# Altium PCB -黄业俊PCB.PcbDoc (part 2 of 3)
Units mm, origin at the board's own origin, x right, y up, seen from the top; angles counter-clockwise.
Board outline 130 x 100.6 mm, 2 copper layers (Top Layer, Bottom Layer); 47 components, 24 nets, 117 pads, 0 vias.
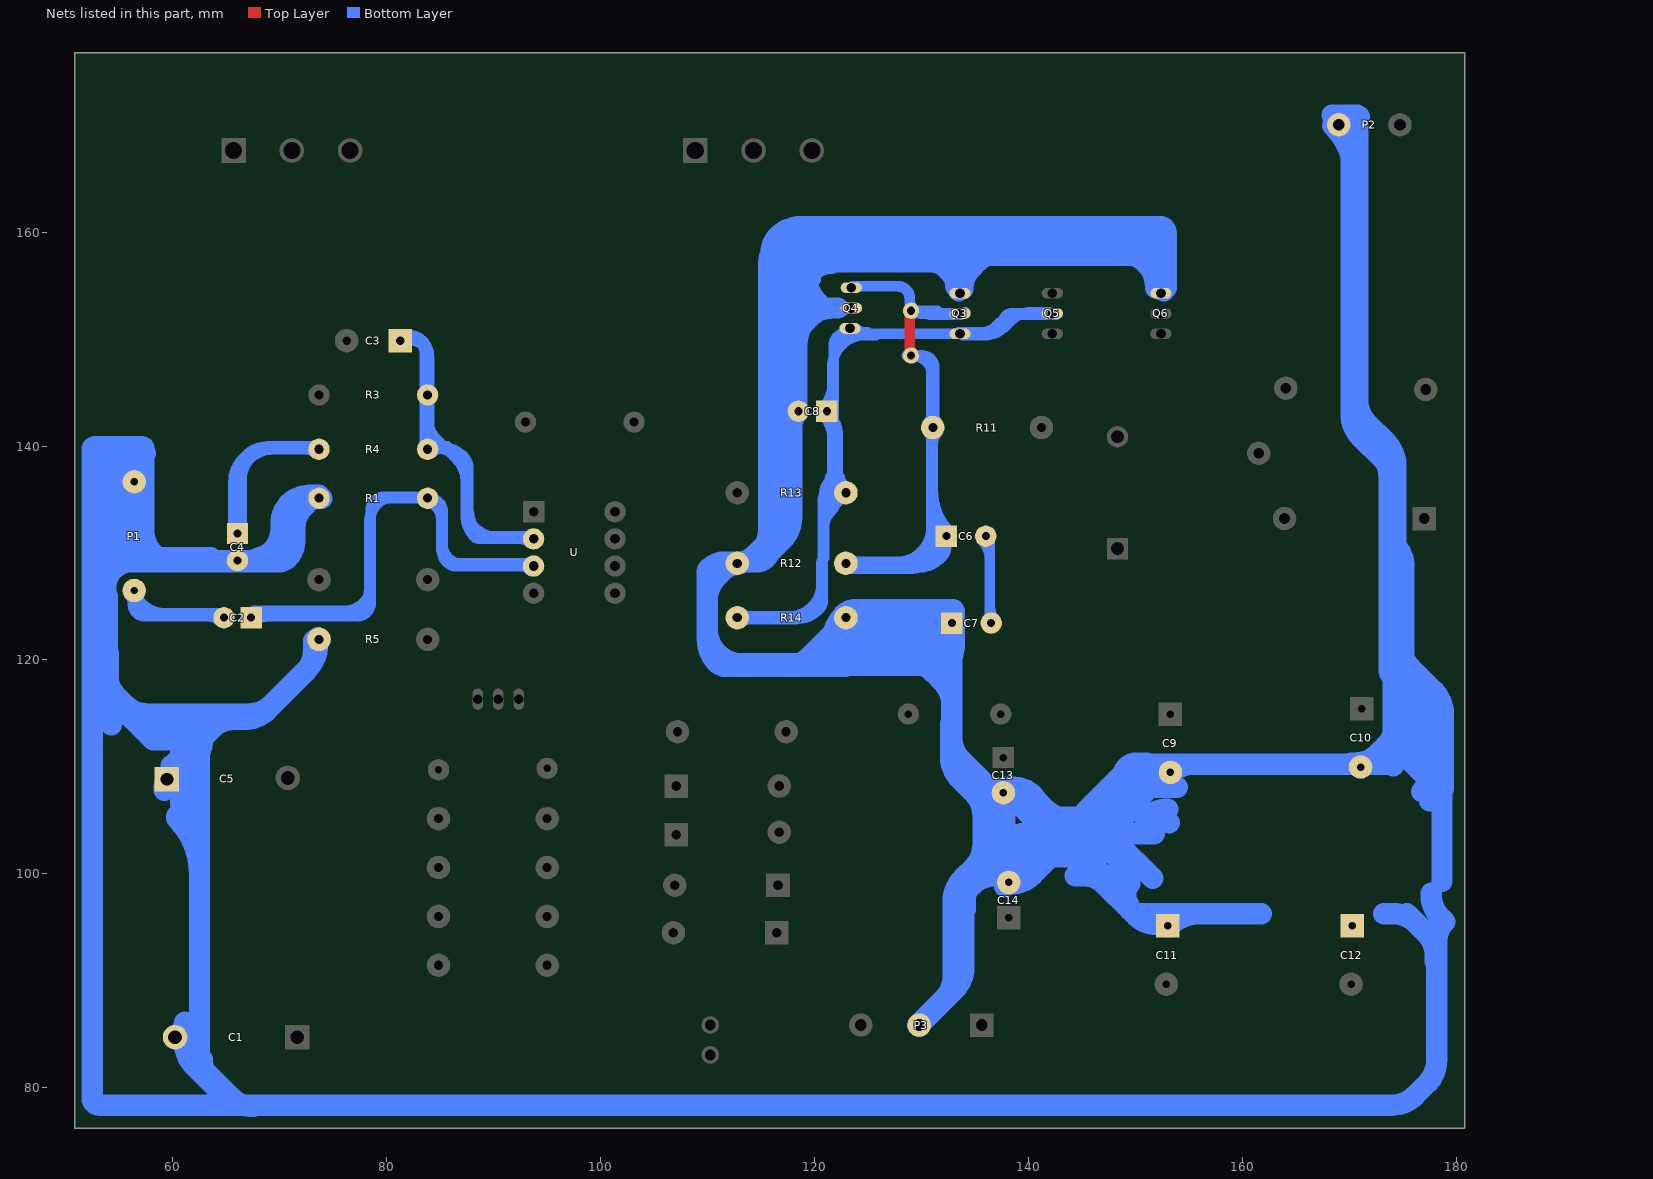
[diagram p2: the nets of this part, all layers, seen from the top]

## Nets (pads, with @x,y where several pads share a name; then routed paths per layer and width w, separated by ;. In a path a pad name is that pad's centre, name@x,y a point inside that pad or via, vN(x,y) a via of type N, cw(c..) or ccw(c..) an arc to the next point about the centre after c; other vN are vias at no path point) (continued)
GND: C1.2 C4.2 C5.1 C7.1 C8.2 C9.2 C10.2 C11.1 C12.1 C13.2 C14.2 P1.1 P2.2 P3.2 Q3.1 Q4.2 Q6.1 R1.2 R5.1 R12.2 R14.2 | length 2136.7
  Bottom Layer w1: 116.713,152.654 Q4.2@122.704,152.654 ; 117.512,147.992 ccw(c117.295,148.209) 117.602,148.209 cw(c120.668,148.209) 118.5,150.377 120.65,152.527 ; 120.105,155.538 cw(c119.888,155.755) 119.888,155.448 ccw(c122.034,155.448) 120.517,153.93 121.232,153.215 ccw(c121.666,153.648) 121.666,153.035 ; 122.331,152.654 ccw(c122.331,153.521) Q4.2@122.944,152.908 ; 122.331,152.654 ccw(c122.331,153.521) Q4.2@122.944,152.908 ; 122.331,152.654 ccw(c122.331,153.521) Q4.2@122.944,152.908 ; 122.331,152.654 ccw(c122.331,153.521) Q4.2@122.944,152.908
  Bottom Layer w2: 52.451,133.604 52.451,139.802 ccw(c52.448,139.802) 52.45,139.804 cw(c52.812,139.443) 52.812,139.954 55.775,139.954 cw(c55.775,139.087) 56.388,139.7 cw(c56.081,139.393) 56.515,139.393 56.515,138.049 ccw(c57.128,137.436) 56.261,137.436 56.261,131.445 ; 52.832,139.446 57.097,139.446 cw(c57.097,139.012) 57.404,139.319 ccw(c57.711,139.012) 57.277,139.012 57.277,132.08 ccw(c60.343,132.08) 58.175,129.912 ccw(c59.073,130.81) 59.073,129.54 63.54,129.54 ; 53.34,129.023 cw(c53.848,128.143) 53.389,129.049 cw(c53.848,128.143) 53.848,129.159 70.104,129.159 ; 53.594,126.55 ccw(c54.461,126.55) 53.848,125.937 53.848,118.745 ccw(c56.914,118.745) 54.746,116.577 55.49,115.833 ccw(c57.658,118.001) 57.658,114.935 67.564,114.935 ; 53.721,121.539 53.721,126.877 cw(c55.858,126.877) 54.347,128.388 cw(c56.515,126.22) 56.515,129.286 ; 53.721,139.954 56.97,139.954 cw(c56.97,139.52) 57.277,139.827 57.277,136.735 cw(c55.543,136.735) 56.769,135.509 56.509,135.249 ccw(c58.026,133.731) 55.88,133.731 ; 53.975,120.65 53.975,117.983 ccw(c57.041,117.983) 54.873,115.815 58.166,112.522 59.182,112.522 ccw(c59.182,115.588) 61.35,113.42 ; 53.975,135.001 53.975,132.842 ccw(c57.041,132.842) 54.873,130.674 55.88,129.667 ; 54.012,136.562 cw(c55.174,135.4) P1.1@56.318,136.58 ; 54.229,130.175 54.229,133.604 cw(c57.295,133.604) 55.127,135.772 P1.1@56.134,136.779 ; 54.238,113.91 cw(c56.406,116.078) 53.34,116.078 53.34,134.063 cw(c55.911,134.063) 54.093,135.881 cw(c56.261,133.713) 56.261,136.779 P1.1@56.388,136.779 ; 54.356,134.112 cw(c55.582,135.338) 53.848,135.338 53.848,135.763 cw(c55.381,135.763) 54.297,136.847 55.155,137.705 cw(c55.372,137.488) 55.372,137.795 ; 54.564,128.605 cw(c56.515,126.654) 56.515,129.413 ; 55.753,114.808 64.135,114.808 ; 55.753,132.969 ccw(c58.819,132.969) 56.651,130.801 57.395,130.057 ccw(c59.563,132.225) 59.563,129.159 61.722,129.159 ; 56.261,114.427 66.675,114.427 ccw(c66.675,117.493) 68.843,115.325 72.254,118.736 ccw(c70.086,120.904) 73.152,120.904 R5.1@73.152,121.793 ; P1.1@56.317,136.581 cw(c54,134.264) 57.277,134.264 ; P1.1@56.317,136.723 ccw(c54,139.04) 57.277,139.04 ; P1.1@56.318,136.723 ccw(c54.066,139.012) 57.277,139.012 ; 56.642,139.954 56.642,132.207 ccw(c59.708,132.207) 57.54,130.039 58.293,129.286 ; 56.896,129.794 ccw(c58.122,131.02) 58.122,129.286 67.183,129.286 ccw(c67.183,132.352) 69.351,130.184 69.587,130.42 ccw(c67.419,132.588) 70.485,132.588 70.485,132.969 ; 56.905,129.912 cw(c59.073,132.08) 56.007,132.08 56.007,133.604 cw(c59.073,133.604) 56.905,135.772 57.023,135.89 57.023,137.331 ccw(c55.289,137.331) 56.515,138.557 ccw(c56.208,138.25) 56.208,138.684 54.737,138.684 ccw(c54.737,135.618) 52.569,137.786 52.451,137.668 52.451,78.92 ccw(c52.885,78.92) 52.578,78.613 ccw(c53.191,79.226) 53.191,78.359 61.341,78.359 ; C5.1@59.182,107.823 cw(c62.248,107.823) 60.08,109.991 63.999,113.91 cw(c66.167,111.742) 66.167,114.808 ; 59.817,110.109 ccw(c59.817,110.416) 60.034,110.199 62.221,112.386 ; 60.071,114.935 67.056,114.935 ccw(c67.056,118.001) 69.224,115.833 72.635,119.244 ccw(c70.467,121.412) 73.533,121.412 R5.1@73.533,122.079 ; C1.2@60.155,84.853 ccw(c59.778,86.106) 61.087,86.106 61.087,84.201 ccw(c64.153,84.201) 61.985,82.033 64.761,79.257 ccw(c66.929,81.425) 66.929,78.359 ; 60.346,105.177 cw(c55.184,100.015) 62.484,100.015 ; 60.346,105.389 ccw(c55.184,110.551) 62.484,110.551 ; 60.706,106.553 60.706,111.655 cw(c61.573,111.655) 60.96,112.268 ; 61.341,107.823 61.341,109.347 cw(c64.407,109.347) 62.239,111.515 ; 61.595,78.359 173.99,78.359 ccw(c173.99,81.425) 176.158,79.257 177.283,80.382 ccw(c175.115,82.55) 178.181,82.55 178.181,93.664 cw(c180.783,93.664) 178.943,95.504 178.571,95.876 cw(c180.739,98.044) 177.673,98.044 177.673,98.171 ; 61.84,110.354 ccw(c59.672,112.522) 62.738,112.522 ; 62.23,111.023 cw(c64.928,111.023) 63.02,112.931 63.726,113.637 cw(c65.634,111.729) 65.634,114.427 66.802,114.427 ; 62.357,86.233 62.357,83.439 ccw(c65.423,83.439) 63.255,81.271 65.396,79.13 ccw(c67.564,81.298) 67.564,78.232 ; 62.484,82.931 62.484,111.252 cw(c65.55,111.252) 63.382,113.42 63.618,113.656 cw(c65.786,111.488) 65.786,114.554 67.183,114.554 ; 62.738,82.652 ccw(c65.436,82.652) 63.528,80.744 65.123,79.149 ccw(c67.031,81.057) 67.031,78.359 67.818,78.359 ; C4.2@66.167,129.286 69.469,129.286 ccw(c69.469,130.556) 70.739,130.556 70.739,133.858 cw(c72.009,133.858) 72.009,135.128 R1.2@73.914,135.128 ; C4.2@66.294,129.159 69.819,129.159 ccw(c69.819,130.46) 70.739,129.54 ccw(c69.206,131.073) 71.374,131.073 71.374,132.207 cw(c74.44,132.207) 72.272,134.375 72.756,134.859 cw(c73.406,134.208) R1.2@73.406,135.128 ; 67.691,129.413 ccw(c67.691,132.479) 69.859,130.311 ; 68.04,129.54 ccw(c68.04,130.248) 68.54,129.747 ccw(c68.54,130.344) 68.962,129.922 69.314,130.274 ccw(c67.406,132.182) 70.104,132.182 70.104,132.82 cw(c72.609,132.82) 70.838,134.592 cw(c72.746,132.684) 72.746,135.382 R1.2@73.66,135.382 ; 72.576,134.679 cw(c73.66,133.595) R1.2@73.66,135.128 ; 73.152,120.784 cw(c74.417,120.784) R5.1@73.715,121.837 ; 111.633,129.032 112.395,129.032 ccw(c112.395,132.098) 114.563,129.93 116.196,131.563 ccw(c114.028,133.731) 117.094,133.731 117.094,153.289 ; R12.2@111.887,129.159 111.642,129.159 ccw(c111.642,126.991) 110.816,128.995 ccw(c111.642,126.991) 110.294,128.689 ccw(c111.642,126.991) 110.109,128.524 ccw(c110.416,128.217) 109.982,128.217 109.982,121.907 ccw(c113.017,121.907) 110.871,119.761 ccw(c111.791,120.681) 111.791,119.38 122.936,119.38 ; 112.141,119.38 117.348,119.38 ccw(c117.348,122.446) 119.516,120.278 121.651,122.413 ccw(c121,123.063) 121.92,123.063 ; R12.2@112.268,129.159 114.554,129.159 ccw(c114.554,130.429) 115.824,130.429 115.824,135.89 cw(c115.951,135.89) 115.951,136.017 115.951,141.224 ccw(c115.951,141.478) 116.205,141.478 ; R12.2@112.522,129.159 113.665,129.159 ccw(c113.665,132.225) 115.833,130.057 116.958,131.182 ccw(c114.79,133.35) 117.856,133.35 117.856,149.956 ccw(c116.555,149.956) 117.475,150.876 117.475,151.13 ; R12.2@112.649,129.032 ccw(c112.649,132.098) 114.817,129.93 ccw(c112.693,132.054) 115.697,132.054 115.697,156.845 cw(c118.763,156.845) 116.595,159.013 116.704,159.122 cw(c118.872,156.954) 118.872,160.02 122.047,160.02 ; R12.2@112.903,129.032 ccw(c112.903,127.192) 111.602,128.493 110.88,127.771 ccw(c113.048,125.603) 109.982,125.603 109.982,123.698 109.982,122.809 ccw(c113.048,122.809) 110.88,120.641 110.989,120.532 ccw(c113.157,122.7) 113.157,119.634 119.454,119.634 ccw(c119.454,120.068) 119.761,119.761 cw(c120.374,119.148) 120.374,120.015 122.958,120.015 ccw(c122.958,120.882) 123.571,120.269 ; 114.173,119.507 131.826,119.507 ; 115.951,139.065 115.951,157.992 cw(c118.088,157.992) 116.577,159.503 cw(c118.745,157.335) 118.745,160.401 136.017,160.401 ; 115.951,155.829 115.951,158.119 cw(c118.088,158.119) 116.577,159.63 cw(c118.745,157.462) 118.745,160.528 136.906,160.528 ; 116.168,156.681 118.101,158.614 cw(c120.269,156.446) 120.269,159.512 121.793,159.512 ; 117.094,139.883 cw(c121.864,139.883) C8.2@118.491,143.256 ; 117.094,146.629 ccw(c121.864,146.629) C8.2@118.491,143.256 ; 117.094,151.511 118.042,152.459 cw(c119.126,151.375) 119.126,152.908 ; 117.744,156.987 118.482,157.725 cw(c120.65,155.557) 120.65,158.623 ; 117.856,141.723 cw(c120.024,141.723) C8.2@118.491,143.256 ; 117.856,144.789 ccw(c120.024,144.789) C8.2@118.491,143.256 ; 117.856,153.416 117.856,154.2 ccw(c116.989,154.2) 117.602,154.813 117.602,155.956 ccw(c117.909,155.956) 117.692,155.739 120.396,153.035 ccw(c120.089,152.728) 120.089,153.162 120.015,153.162 ccw(c118.789,153.162) 119.656,154.029 119.38,154.305 cw(c119.687,154.612) 119.253,154.612 119.253,155.448 cw(c120.479,155.448) 119.612,156.315 120.006,156.709 cw(c122.174,154.541) 122.174,157.607 124.841,157.607 ; 117.983,150.876 119.38,152.273 ; C8.2@118.364,143.637 118.364,149.606 cw(c121.43,149.606) 119.262,151.774 119.498,152.01 cw(c121.666,149.842) 121.666,152.908 122.174,152.908 119.634,152.908 ; 118.999,157.861 131.944,157.861 cw(c131.944,155.693) 133.477,157.226 cw(c133.17,156.919) 133.604,156.919 133.678,156.919 ccw(c133.678,159.985) 135.846,157.817 ; 119.244,156.328 cw(c121.412,154.16) 121.412,157.226 128.007,157.226 ccw(c128.007,159.394) 129.54,157.861 ; 119.244,156.709 cw(c121.412,154.541) 121.412,157.607 123.317,157.607 ; 119.371,156.582 cw(c121.539,154.414) 121.539,157.48 127,157.48 ; 119.56,156.644 120.65,157.734 ccw(c121.876,158.96) 121.876,157.226 132.842,157.226 ; 119.77,156.346 cw(c121.588,154.528) 121.588,157.099 ; 119.888,160.528 152.01,160.528 ; 122.047,121.564 cw(c125.324,121.564) 123.007,123.881 cw(c125.017,121.871) 125.017,124.714 ; 122.047,122.602 cw(c123.363,122.602) R14.2@122.966,123.857 ; R14.2@122.682,124.206 cw(c123.908,122.98) 123.908,124.714 130.801,124.714 cw(c130.801,122.546) 132.334,124.079 cw(c131.108,122.853) 132.842,122.853 cw(c130.897,122.853) 132.272,121.477 ccw(c131.51,120.715) 131.51,121.793 ; R14.2@122.809,124.079 131.699,124.079 ; R14.2@123.317,123.19 129.667,123.19 cw(c129.667,122.555) 130.302,122.555 130.302,122.047 cw(c129.032,122.047) 129.032,120.777 123.952,120.777 cw(c123.952,121.285) 123.444,121.285 ; 124.46,119.761 128.905,119.761 cw(c128.905,116.695) 131.073,118.863 131.944,117.992 cw(c129.776,115.824) 132.842,115.824 132.842,112.776 ; 125.017,123.19 cw(c125.017,126.033) 123.007,124.023 ccw(c127.776,128.792) 127.776,122.047 ; 125.984,158.623 130.429,158.623 cw(c130.429,155.557) 132.597,157.725 cw(c131.086,156.214) 133.223,156.214 133.223,155.321 ; 127,158.369 129.286,158.369 cw(c129.286,155.303) 131.454,157.471 132.684,156.241 cw(c131.383,154.94) 133.223,154.94 ccw(c133.836,155.553) 133.836,154.686 133.858,154.686 cw(c136.617,154.686) 134.666,156.637 135.246,157.217 cw(c137.414,155.049) 137.414,158.115 138.684,158.115 ; 128.143,122.936 128.905,122.936 cw(c128.905,119.87) 131.073,122.038 131.99,121.121 cw(c131.773,120.904) 132.08,120.904 ; 128.651,124.714 132.969,124.714 cw(c132.662,124.407) 133.096,124.407 133.096,121.158 ; P3.2@129.635,85.82 132.071,88.256 ccw(c129.903,90.424) 132.969,90.424 132.969,97.409 cw(c136.035,97.409) 133.867,99.577 134.865,100.575 ccw(c132.697,102.743) 135.763,102.743 135.763,105.41 ccw(c132.697,105.41) 134.865,107.578 133.613,108.83 cw(c135.781,110.998) 132.715,110.998 132.715,114.046 ; 129.776,124.714 cw(c129.776,120.378) C7.1@132.842,123.444 ; P3.2@129.794,85.852 133.087,89.145 ccw(c130.919,91.313) 133.985,91.313 133.985,97.028 cw(c137.051,97.028) 134.883,99.196 136.389,100.702 cw(c138.557,98.534) 138.557,101.6 145.682,101.6 ccw(c145.682,104.635) 147.828,102.489 ; 129.921,157.226 130.683,157.226 cw(c130.683,154.16) 132.851,156.328 133.387,155.792 cw(c133.17,155.575) 133.477,155.575 ; 129.921,157.988 130.175,157.988 cw(c130.175,154.922) 132.343,157.09 ; 130.556,122.936 cw(c129.667,122.936) 129.667,122.047 123.19,122.047 ccw(c124.46,122.047) 124.46,120.777 130.556,120.777 ccw(c130.556,122.047) 131.826,122.047 131.826,122.936 ccw(c130.556,122.936) 130.556,124.206 123.317,124.206 ccw(c123.317,122.936) 122.047,122.936 122.047,119.634 ccw(c122.174,119.634) 122.174,119.507 131.699,119.507 ccw(c131.699,120.777) 132.969,120.777 132.969,122.809 ccw(c131.699,122.809) 131.699,124.079 ; 131.309,124.079 cw(c131.309,121.911) C7.1@132.842,123.444 ; 131.826,121.717 cw(c133.802,121.717) C7.1@132.842,123.444 ; 131.826,122.308 cw(c132.969,122.308) C7.1@132.842,123.444 ; 133.35,154.94 cw(c135.496,154.94) 133.979,156.458 ; Q3.1@133.477,154.527 133.477,156.718 ; 133.604,154.94 cw(c136.057,154.94) 134.322,156.674 134.611,156.963 cw(c136.779,154.795) 136.779,157.861 150.114,157.861 cw(c150.114,154.795) 152.282,156.963 ; 133.858,98.044 134.738,98.924 cw(c136.906,96.756) 136.906,99.822 ; 133.858,110.363 136.643,107.578 cw(c134.475,105.41) 137.541,105.41 137.541,103.505 cw(c134.475,103.505) 136.643,101.337 134.741,99.435 ccw(c136.258,97.917) 134.112,97.917 134.112,96.827 cw(c133.678,96.827) 133.985,96.52 ; 133.858,155.067 133.858,155.194 cw(c136.924,155.194) 134.756,157.362 137.541,160.147 ; 135.509,160.528 138.347,160.528 ; 135.763,108.458 ccw(c137.668,110.363) C13.2@137.668,107.669 ; 136.144,159.893 138.811,159.893 ; 136.779,160.02 118.986,160.02 ccw(c118.986,156.985) 116.84,159.131 117.392,159.131 cw(c117.392,157.397) 118.618,158.623 cw(c119.538,157.703) 119.538,159.004 150.179,159.004 cw(c150.179,156.402) 152.019,158.242 ; C13.2@137.16,106.676 ccw(c135.925,106.676) 136.798,107.55 133.74,110.608 ; C13.2@137.287,107.188 C13.2@137.287,107.569 ; C13.2@137.414,106.934 133.74,110.608 ; C13.2@137.668,107.469 cw(c137.668,102.629) 141.091,106.051 ; C13.2@137.668,107.95 140.961,104.657 ccw(c143.129,106.825) 143.129,103.759 150.823,103.759 ccw(c150.823,104.193) 151.13,103.886 ; C13.2@137.668,108.077 138.622,108.077 cw(c138.622,105.475) 140.462,107.315 cw(c139.849,106.702) 140.716,106.702 ; C13.2@137.688,107.471 cw(c138.311,104.402) 140.525,106.617 ; 137.795,100.348 ccw(c139.337,100.348) C14.2@138.247,99.258 ; C13.2@137.795,107.696 137.795,98.806 cw(c138.408,98.193) 138.408,99.06 ccw(c138.408,101.872) 140.397,99.884 143.12,102.607 cw(c145.288,100.439) 145.288,103.505 ; C13.2@137.922,107.569 138.303,107.569 cw(c138.303,104.503) 140.471,106.671 141.469,105.673 ccw(c143.637,107.841) 143.637,104.775 146.431,104.775 ccw(c146.431,107.841) 148.599,105.673 150.913,107.987 cw(c151.13,107.77) 151.13,108.077 ; C14.2@138.089,99.137 ccw(c136.906,98.457) 136.906,99.822 ; C14.2@138.105,99.258 ccw(c136.095,101.268) 138.938,101.268 ; C14.2@138.124,99.273 ccw(c137.26,100.711) 138.938,100.711 ; C14.2@138.176,99.287 ccw(c138.176,101.675) 139.864,99.986 ; C14.2@138.187,99.286 ccw(c138.382,101.14) 139.7,99.822 142.739,102.861 cw(c144.907,100.693) 144.907,103.759 ; C14.2@138.811,99.822 136.906,99.822 ; 139.319,101.727 143.637,101.727 cw(c143.637,98.661) 145.805,100.829 149.12,97.514 cw(c148.253,96.647) 149.479,96.647 ; 139.319,103.759 cw(c138.706,103.146) 139.573,103.146 139.573,102.244 cw(c137.405,102.244) 138.938,100.711 ; 139.573,107.569 140.961,106.181 ccw(c143.129,108.349) 143.129,105.283 144.272,105.283 ccw(c144.272,108.349) 146.44,106.181 149.516,109.257 ccw(c149.299,109.474) 149.606,109.474 149.606,109.601 ; 139.827,107.823 141.596,106.054 ccw(c143.764,108.222) 143.764,105.156 ccw(c143.764,107.609) 145.498,105.874 146.676,107.052 cw(c148.844,104.884) 148.844,107.95 149.606,107.95 ; 139.954,106.68 141.088,105.546 ccw(c143.256,107.714) 143.256,104.648 144.78,104.648 ccw(c144.78,107.714) 146.948,105.546 149.225,107.823 cw(c150.145,107.823) 149.494,108.473 ; 140.081,107.188 141.215,106.054 ccw(c143.383,108.222) 143.383,105.156 146.05,105.156 ccw(c146.05,108.222) 148.218,106.054 149.247,107.083 cw(c150.114,106.216) 150.114,107.442 cw(c151.34,107.442) 150.473,108.309 151.502,109.338 cw(c153.67,107.17) 153.67,110.236 173.81,110.236 cw(c173.81,109.802) 174.117,110.109 ; 140.208,106.68 140.834,106.054 ccw(c143.002,108.222) 143.002,105.156 145.034,105.156 ccw(c145.034,108.222) 147.202,106.054 149.337,108.189 cw(c149.987,107.538) 149.987,108.458 ; 140.97,103.505 145.034,103.505 cw(c145.034,100.439) 147.202,102.607 148.581,101.228 cw(c146.413,99.06) 149.479,99.06 ; 141.224,104.267 147.701,104.267 ccw(c147.701,105.537) 148.971,105.537 148.971,109.347 cw(c149.86,109.347) 149.86,110.236 C9.2@153.416,110.236 ; 144.399,99.822 145.186,99.822 cw(c145.186,97.124) 147.094,99.032 149.225,96.901 ; 145.288,104.013 145.796,104.013 cw(c145.796,100.947) 147.964,103.115 ; 145.669,157.988 148.87,157.988 cw(c148.87,154.984) 150.994,157.108 cw(c148.826,154.94) 151.892,154.94 151.892,154.813 ; 147.066,99.949 ccw(c147.986,99.949) 147.335,99.299 ; 147.066,103.886 147.066,103.759 ccw(c147.828,103.759) 147.828,102.997 cw(c147.828,101.727) 149.098,101.727 149.098,97.536 ccw(c150.368,97.536) 150.368,96.266 ; 147.193,160.528 152.347,160.528 cw(c152.347,160.094) 152.654,160.401 cw(c152.041,159.788) 152.908,159.788 152.908,154.813 ; 147.447,99.797 ccw(c150.145,99.797) 148.237,97.889 150.086,96.04 ccw(c151.994,97.948) 151.994,95.25 C11.1@153.162,95.25 ; 149.479,157.861 149.733,157.861 cw(c149.733,154.795) 151.901,156.963 cw(c150.39,155.452) 152.527,155.452 ; 150.3,108.136 cw(c153.289,105.147) 153.289,109.374 ccw(c153.289,107.906) 152.251,108.944 ; 150.495,160.274 cw(c150.802,159.967) 150.802,160.401 151.301,160.401 cw(c151.301,158.667) 152.527,159.893 Q6.1@152.527,154.559 ; 150.677,108.513 cw(c152.835,106.354) C9.2@153.275,109.375 ; 150.867,105.147 cw(c153.035,102.979) 153.035,106.045 ; 151.003,105.664 cw(c151.003,102.598) 153.171,104.766 ; 151.13,110.363 150.114,110.363 ccw(c150.114,109.093) 148.844,109.093 148.844,107.569 cw(c147.574,107.569) 147.574,106.299 147.574,106.045 cw(c146.304,106.045) 146.304,104.775 141.732,104.775 cw(c141.732,106.045) 140.462,106.045 ccw(c141.478,106.045) 141.478,105.029 145.415,105.029 ccw(c145.415,106.045) 146.431,106.045 cw(c147.32,106.045) 147.32,106.934 ccw(c147.32,106.299) 146.685,106.299 cw(c145.669,106.299) 145.669,105.283 ccw(c145.669,106.553) 146.939,106.553 cw(c146.939,106.045) 147.447,106.045 146.685,106.045 ccw(c146.685,105.918) 146.558,105.918 147.32,105.918 ccw(c147.32,107.188) 148.59,107.188 148.59,106.553 cw(c147.32,106.553) 147.32,105.283 143.891,105.283 ccw(c143.891,104.013) 142.621,104.013 144.018,104.013 ccw(c144.018,107.079) 146.186,104.911 cw(c146.514,105.239) 146.05,105.239 ccw(c146.05,107.28) 147.493,105.837 ccw(c147.493,107.983) 149.011,106.466 ccw(c147.881,107.596) 149.479,107.596 146.921,105.038 cw(c144.753,107.206) 144.753,104.14 cw(c147.447,104.14) 145.542,106.045 148.708,109.211 cw(c150.876,107.043) 150.876,110.109 153.363,110.109 cw(c153.363,109.675) 153.67,109.982 ccw(c153.977,110.289) C9.2@153.977,109.855 ; 151.208,110.236 cw(c151.208,107.393) 153.218,109.403 ccw(c151.515,107.7) 151.515,110.109 ; 151.638,99.568 148.345,102.861 ccw(c146.177,100.693) 146.177,103.759 144.907,103.759 ; 151.765,103.759 144.907,103.759 ; Q6.1@152.654,154.527 152.654,156.718 ; C11.1@152.958,95.059 ccw(c150.368,92.884) 150.368,96.266 ; C11.1@153.106,95.052 cw(c156.036,92.122) 156.036,96.266 ; C9.2@153.195,109.509 cw(c151.13,110.282) 151.13,108.077 ; C9.2@153.289,109.982 148.472,105.165 cw(c146.304,107.333) 146.304,104.267 141.986,104.267 139.678,101.959 cw(c138.811,102.826) 138.811,101.6 cw(c139.424,101.6) 138.991,102.034 cw(c139.118,102.161) 138.938,102.161 138.938,100.711 ; C9.2@153.36,109.403 cw(c155.37,107.393) 155.37,110.236 ; 153.924,108.077 151.13,108.077 ; 161.798,96.266 150.368,96.266 ; P2.2@168.402,170.942 170.635,170.942 ; P2.2@168.458,169.982 cw(c163.382,164.906) 170.561,164.906 ; P2.2@168.966,169.982 cw(c166.036,167.052) 170.18,167.052 ; P2.2@168.972,169.977 cw(c165.523,165.963) 170.815,165.963 ; P2.2@169.011,169.956 cw(c168.608,168.437) 170.18,168.437 ; P2.2@169.126,170.008 cw(c170.635,169.256) 170.635,170.942 ; C10.2@170.18,110.363 170.561,110.363 ccw(c170.561,113.429) 172.729,111.261 173.346,111.878 ccw(c171.178,114.046) 174.244,114.046 174.244,116.332 ; 170.18,144.78 cw(c168.647,143.247) 170.815,143.247 170.815,143.116 ccw(c173.85,143.116) 171.704,140.97 cw(c171.091,140.357) 171.958,140.357 ; 170.18,146.304 170.18,168.91 ; 170.18,147.574 170.18,143.002 ccw(c173.246,143.002) 170.561,141.522 ccw(c173.246,143.002) 171.078,140.834 173.219,138.693 cw(c171.051,136.525) 174.117,136.525 174.117,113.411 ccw(c177.183,113.411) 175.015,111.243 177.546,108.712 ; 170.307,146.558 170.307,143.51 ccw(c173.373,143.51) 171.205,141.342 173.219,139.328 cw(c171.051,137.16) 174.117,137.16 174.117,126.111 ; 170.688,170.202 cw(c171.555,170.202) 170.942,170.815 ccw(c170.635,170.508) 170.635,170.942 ; 170.815,166.37 170.815,169.917 ; 170.815,167.259 170.815,144.272 ccw(c173.881,144.272) 171.713,142.104 173.473,140.344 cw(c171.305,138.176) 174.371,138.176 174.371,130.258 ccw(c176.105,130.258) 174.879,129.032 ; 171.577,140.716 ccw(c171.884,140.716) 171.667,140.499 172.838,139.328 cw(c170.67,137.16) 173.736,137.16 173.736,119.104 ccw(c174.603,119.104) 173.99,118.491 cw(c172.764,117.265) 174.498,117.265 ; 173.228,96.266 174.117,96.266 cw(c174.117,93.2) 176.285,95.368 177.546,94.107 ; 174.117,130.937 174.235,130.819 cw(c172.067,128.651) 175.133,128.651 175.133,122.555 ; 174.244,123.593 174.244,115.951 ccw(c177.31,115.951) 175.142,113.783 176.648,112.277 cw(c174.48,110.109) 177.546,110.109 177.546,106.807 ; 174.371,116.332 174.371,114.681 ccw(c177.437,114.681) 175.269,112.513 176.394,111.388 cw(c174.226,109.22) 177.292,109.22 ; 174.371,128.016 cw(c172.531,126.176) 175.133,126.176 175.133,114.046 ccw(c178.199,114.046) 176.031,111.878 ; 174.498,117.348 176.521,115.325 cw(c174.353,113.157) 177.419,113.157 177.419,109.229 cw(c175.251,109.229) 176.784,107.696 ; 174.752,122.936 174.752,120.904 ccw(c177.818,120.904) 175.65,118.736 177.918,116.468 cw(c175.75,114.3) 178.816,114.3 178.816,107.95 ; 174.879,124.587 174.879,121.412 ; 175.387,96.266 177.156,94.497 cw(c174.988,92.329) 178.054,92.329 178.054,91.821 ; 175.514,115.697 175.514,115.443 ccw(c178.58,115.443) 176.412,113.275 ; 178.689,99.314 178.689,114.217 ccw(c176.955,114.217) 178.181,115.443 175.777,117.847 cw(c177.945,120.015) 174.879,120.015 174.879,121.412 ; 178.816,108.839 178.816,114.935 ccw(c175.75,114.935) 177.918,117.103 175.777,119.244 cw(c177.945,121.412) 174.879,121.412 ; 178.816,109.461 178.816,114.681 ; 131.699,124.079 cw(c131.699,122.733) C7.1@132.842,123.444 ; 132.842,112.776 ccw(c135.908,112.776) 133.74,110.608 ; 132.842,112.776 ccw(c135.908,112.776) 133.74,110.608 ; 132.842,112.776 C7.1@132.842,123.444 ; C13.2@137.668,107.669 cw(c137.668,110.057) 135.98,108.368 ccw(c137.668,110.057) C13.2@137.668,107.669 ; 111.521,128.412 cw(c112.776,127.158) 112.776,128.932 ccw(c112.776,127.158) 111.521,128.412 ; R12.2@112.776,129.132 ccw(c112.776,131.52) 114.464,129.831 cw(c112.776,131.52) R12.2@112.776,129.132
NetC2_1: C2.1 R1.1 U.3 | length 141
  Bottom Layer w1: C2.1@67.183,124.079 77.216,124.079 ccw(c77.216,125.349) 78.486,125.349 78.486,133.985 cw(c79.756,133.985) 79.756,135.255 R1.1@84.074,135.255 ; C2.1@67.564,124.587 76.011,124.587 ccw(c76.011,127.189) 77.851,125.349 ccw(c76.625,126.575) 78.359,126.575 78.359,132.74 cw(c81.057,132.74) 79.149,134.648 cw(c80.307,133.49) 80.307,135.128 R1.1@83.185,135.128 ; C2.1@67.664,123.598 cw(c68.824,122.438) 68.824,124.079 ; 74.295,124.079 75.464,124.079 ccw(c75.464,127.083) 77.588,124.959 ccw(c75.42,127.127) 78.486,127.127 78.486,129.54 ; 81.788,135.128 82.702,135.128 cw(c82.702,132.43) 84.61,134.338 cw(c83.452,133.18) 85.09,133.18 85.09,130.512 ccw(c86.824,130.512) 85.598,129.286 ; 82.306,135.255 cw(c82.306,133.614) R1.1@83.466,134.774 ; R1.1@83.566,135.128 83.947,135.128 cw(c83.947,133.858) 85.217,133.858 85.217,130.048 ccw(c86.487,130.048) 86.487,128.778 U.3@93.853,128.778 ; 85.09,130.946 ccw(c87.258,130.946) 85.725,129.413 ccw(c86.645,130.333) 86.645,129.032 U.3@93.599,129.032 ; 85.217,132.334 85.217,130.766 ccw(c86.951,130.766) 85.725,129.54 ccw(c87.258,131.073) 87.258,128.905 89.281,128.905 ; 85.988,128.905 U.3@93.853,128.905 ; 86.623,128.905 U.3@93.98,128.905 ; 86.917,128.905 93.546,128.905 ccw(c93.546,129.339) 93.853,129.032 U.3@93.98,129.032 ; U.3@93.345,128.397 ccw(c93.345,128.651) U.3@93.599,128.651 ; U.3@93.372,129.132 cw(c92.519,129.985) 92.519,128.778 cw(c92.519,127.571) U.3@93.372,128.424 ; 91.906,129.032 cw(c91.906,126.958) U.3@93.372,128.424 ; 91.906,129.032 cw(c91.906,126.958) U.3@93.372,128.424 ; 91.906,129.032 cw(c91.906,126.958) U.3@93.372,128.424 ; 92.212,128.905 cw(c92.212,127.264) U.3@93.372,128.424 ; 92.212,128.905 cw(c92.212,127.264) U.3@93.372,128.424 ; 92.212,128.905 cw(c92.212,127.264) U.3@93.372,128.424 ; 92.212,128.905 cw(c92.212,127.264) U.3@93.372,128.424 ; 92.212,128.905 cw(c92.212,127.264) U.3@93.372,128.424 ; 92.212,128.905 cw(c92.212,127.264) U.3@93.372,128.424 ; 92.212,128.905 cw(c92.212,127.264) U.3@93.372,128.424
NetC2_2: C2.2 P1.2 | length 52.1
  Bottom Layer w1: P1.2@56.261,126.619 56.261,125.197 ; P1.2@56.261,126.746 ccw(c59.02,126.746) 57.069,124.795 ccw(c58.491,126.216) 58.491,124.206 60.198,124.206 60.452,124.206 C2.2@64.77,124.206 ; P1.2@56.388,126.619 ccw(c57.921,126.619) 56.837,125.535 57.141,125.231 ccw(c59.309,127.399) 59.309,124.333 C2.2@64.389,124.333 ; 62.643,124.333 cw(c62.643,121.825) C2.2@64.416,123.598 ; 62.95,124.206 cw(c62.95,122.132) C2.2@64.416,123.598 ; C2.2@64.922,124.079 57.379,124.079 ; P1.2@55.964,126.068 cw(c55.246,125.35) 56.261,125.35 ; P1.2@55.964,126.068 cw(c55.246,125.35) 56.261,125.35 ; P1.2@55.964,126.068 cw(c55.246,125.35) 56.261,125.35 ; P1.2@55.964,126.068 cw(c55.246,125.35) 56.261,125.35 ; P1.2@55.964,126.068 cw(c55.246,125.35) 56.261,125.35 ; 56.261,125.19 cw(c57.19,125.19) P1.2@56.703,125.981 ; 56.261,125.19 cw(c57.19,125.19) P1.2@56.703,125.981 ; 56.261,125.19 cw(c57.19,125.19) P1.2@56.703,125.981 ; 56.261,125.19 cw(c57.19,125.19) P1.2@56.703,125.981 ; 56.261,125.19 cw(c57.19,125.19) P1.2@56.703,125.981 ; 56.261,125.197 ccw(c57.379,125.197) 57.379,124.079 ; 56.261,125.197 ccw(c57.379,125.197) 57.379,124.079 ; 56.261,125.197 ccw(c57.379,125.197) 57.379,124.079 ; 63.256,124.079 cw(c63.256,122.438) C2.2@64.416,123.598 ; 63.256,124.079 cw(c63.256,122.438) C2.2@64.416,123.598 ; 63.256,124.079 cw(c63.256,122.438) C2.2@64.416,123.598 ; 63.256,124.079 cw(c63.256,122.438) C2.2@64.416,123.598 ; 63.256,124.079 cw(c63.256,122.438) C2.2@64.416,123.598
NetC3_1: C3.1 R3.1 R4.2 U.2 | length 154.4
  Bottom Layer w1: C3.1@81.407,150.368 82.086,150.368 cw(c82.086,148.634) 83.312,149.86 cw(c81.779,148.327) 83.947,148.327 83.947,142.088 ccw(c86.645,142.088) 84.737,140.18 ; 83.693,141.214 ccw(c85.334,141.214) R4.2@84.174,140.054 ; 83.693,141.351 ccw(c85.226,141.351) 84.142,140.267 ccw(c85.511,141.636) 85.511,139.7 85.725,139.7 ; 83.693,143.129 83.693,142.469 ccw(c86.391,142.469) 84.483,140.561 ; 83.693,143.266 cw(c85.334,143.266) R3.1@84.174,144.426 ; R3.1@83.693,145.034 83.693,141.053 ; R3.1@83.82,144.78 83.82,142.596 ccw(c86.518,142.596) 84.61,140.688 86.586,138.712 cw(c84.678,136.804) 87.376,136.804 87.376,135.128 ; R4.2@83.947,139.827 84.455,139.827 cw(c84.455,136.761) 86.623,138.929 cw(c84.805,137.111) 87.376,137.111 87.376,133.762 ccw(c88.677,133.762) 87.757,132.842 88.256,132.343 ccw(c90.424,134.511) 89.551,131.572 ccw(c90.424,134.511) 90.424,131.445 U.2@93.853,131.445 ; R4.2@84.143,140.081 cw(c84.967,141.053) 83.693,141.053 ; R4.2@84.182,139.355 cw(c85.282,138.308) 85.282,139.827 ; R4.2@84.239,139.427 cw(c84.976,138.948) 84.976,139.827 ; 87.376,134.874 87.376,138.325 ccw(c86.509,138.325) 87.122,138.938 ccw(c84.976,136.792) 84.976,139.827 ; 87.376,135.509 87.376,133.591 ccw(c90.411,133.591) 88.265,131.445 ; 87.503,134.546 cw(c87.069,134.546) 87.376,134.239 87.376,134.112 ccw(c90.442,134.112) 88.274,131.944 ; 88.572,131.318 U.2@93.726,131.318 ; 88.646,131.572 U.2@93.472,131.572 ; U.2@93.599,131.699 U.2@93.853,131.699 ; U.2@93.98,131.318 90.039,131.318 cw(c90.039,133.455) 88.528,131.944 cw(c90.696,134.112) 87.63,134.112 87.63,137.839 ccw(c85.896,137.839) 87.122,139.065 ccw(c85.282,137.225) 85.282,139.827 ; 82.448,149.86 cw(c82.448,148.742) 83.566,148.742 ; 82.448,149.86 cw(c82.448,148.742) 83.566,148.742 ; 82.448,149.86 cw(c82.448,148.742) 83.566,148.742 ; R4.2@83.566,140.081 ccw(c83.82,140.081) R4.2@83.82,139.827 ; R4.2@83.566,140.081 ccw(c83.82,140.081) R4.2@83.82,139.827 ; R4.2@83.566,140.081 ccw(c83.82,140.081) R4.2@83.82,139.827 ; R4.2@83.566,140.081 83.566,148.742 ; 83.566,141.52 ccw(c85.64,141.52) R4.2@84.174,140.054 ; 83.566,141.52 ccw(c85.64,141.52) R4.2@84.174,140.054 ; 83.566,141.52 ccw(c85.64,141.52) R4.2@84.174,140.054 ; 83.566,141.52 ccw(c85.64,141.52) R4.2@84.174,140.054 ; 83.566,141.52 ccw(c85.64,141.52) R4.2@84.174,140.054 ; 83.566,142.96 cw(c85.64,142.96) R3.1@84.174,144.426 ; 83.566,142.96 cw(c85.64,142.96) R3.1@84.174,144.426 ; 83.566,142.96 cw(c85.64,142.96) R3.1@84.174,144.426 ; 83.566,142.96 cw(c85.64,142.96) R3.1@84.174,144.426 ; 83.566,142.96 cw(c85.64,142.96) R3.1@84.174,144.426 ; 83.566,146.6 ccw(c85.64,146.6) R3.1@84.174,145.134 ; 83.566,146.6 ccw(c85.64,146.6) R3.1@84.174,145.134 ; 83.566,146.6 ccw(c85.64,146.6) R3.1@84.174,145.134 ; 83.566,146.6 ccw(c85.64,146.6) R3.1@84.174,145.134 ; 83.566,146.6 ccw(c85.64,146.6) R3.1@84.174,145.134 ; 83.693,141.053 ccw(c85.427,141.053) 84.201,139.827 84.976,139.827 ; R4.2@83.82,139.827 85.282,139.827 ; R4.2@84.174,139.346 cw(c85.64,137.88) 85.64,139.954 ; R4.2@84.174,139.346 cw(c85.64,137.88) 85.64,139.954 ; R4.2@84.174,139.346 cw(c85.64,137.88) 85.64,139.954 ; 91.906,131.572 cw(c91.906,129.498) U.2@93.372,130.964 ; 91.906,131.572 cw(c91.906,129.498) U.2@93.372,130.964 ; 91.906,131.572 cw(c91.906,129.498) U.2@93.372,130.964 ; 91.906,131.572 cw(c91.906,129.498) U.2@93.372,130.964 ; 92.519,131.318 cw(c92.519,130.111) U.2@93.372,130.964 ; 92.519,131.318 ccw(c92.519,132.525) 93.372,131.672 cw(c92.519,132.525) 92.519,131.318 ; 92.519,131.318 cw(c92.519,130.111) U.2@93.372,130.964 ; U.2@93.372,130.964 ccw(c92.212,129.804) 92.212,131.445 cw(c92.212,129.804) U.2@93.372,130.964
NetC4_1: C4.1 R4.1 | length 59.9
  Bottom Layer w1: C4.1@65.659,132.207 65.659,136.652 cw(c68.725,136.652) 66.557,138.82 66.883,139.146 cw(c68.834,137.195) 68.834,139.954 R4.1@73.533,139.954 ; 65.659,133.953 ccw(c68.167,133.953) C4.1@66.394,132.18 ; C4.1@65.786,131.445 65.786,136.144 cw(c68.852,136.144) 65.913,137.017 cw(c68.852,136.144) 66.684,138.312 67.174,138.802 cw(c69.342,136.634) 69.342,139.7 R4.1@73.914,139.7 ; C4.1@66.421,132.461 66.421,136.931 cw(c69.119,136.931) 67.211,138.839 67.75,139.378 cw(c68.834,138.294) 68.834,139.827 ; C4.1@65.532,131.572 cw(c66.167,131.572) C4.1@66.167,132.207 ; C4.1@65.532,131.572 cw(c66.167,131.572) C4.1@66.167,132.207 ; C4.1@65.532,131.572 cw(c66.167,131.572) C4.1@66.167,132.207 ; 65.913,133.34 ccw(c67.554,133.34) C4.1@66.394,132.18 ; 65.913,133.34 ccw(c67.554,133.34) C4.1@66.394,132.18 ; 65.913,133.34 ccw(c67.554,133.34) C4.1@66.394,132.18 ; C4.1@66.394,132.18 cw(c67.86,133.646) 65.786,133.646 ccw(c67.86,133.646) C4.1@66.394,132.18 ; 71.84,139.954 cw(c71.84,137.88) R4.1@73.306,139.346 ; 71.84,139.954 cw(c71.84,137.88) R4.1@73.306,139.346 ; 71.84,139.954 cw(c71.84,137.88) R4.1@73.306,139.346 ; 71.84,139.954 cw(c71.84,137.88) R4.1@73.306,139.346 ; 72.453,139.7 cw(c72.453,138.493) R4.1@73.306,139.346 ; 72.453,139.7 ccw(c72.453,140.907) 73.306,140.054 cw(c72.453,140.907) 72.453,139.7 ; 72.453,139.7 cw(c72.453,138.493) R4.1@73.306,139.346
NetC6_1: C6.1 pad.0@129.032,152.654 pad.1@129.032,148.463 Q3.2 Q4.1 R11.1 R12.1 | length 224.7
  Top Layer w1: pad.1@128.905,148.336 128.905,152.4 cw(c129.159,152.4) pad.0@129.159,152.654 ; 128.905,149.402 ccw(c129.971,149.402) pad.1@129.217,148.648 ; 128.905,149.402 ccw(c129.971,149.402) pad.1@129.217,148.648 ; 128.905,149.402 ccw(c129.971,149.402) pad.1@129.217,148.648 ; 128.905,149.402 ccw(c129.971,149.402) pad.1@129.217,148.648 ; 128.905,149.402 ccw(c129.971,149.402) pad.1@129.217,148.648 ; 128.905,151.715 cw(c129.971,151.715) pad.0@129.217,152.469 ; 128.905,151.715 cw(c129.971,151.715) pad.0@129.217,152.469 ; 128.905,151.715 cw(c129.971,151.715) pad.0@129.217,152.469 ; 128.905,151.715 cw(c129.971,151.715) pad.0@129.217,152.469 ; 128.905,151.715 cw(c129.971,151.715) pad.0@129.217,152.469
  Bottom Layer w1: R12.1@122.428,128.651 129.667,128.651 ccw(c129.667,131.717) 131.15,129.034 ccw(c129.667,131.717) 131.835,129.549 ccw(c130.63,130.754) 132.206,130.106 ccw(c130.63,130.754) 132.334,130.754 C6.1@132.334,131.826 ; R12.1@122.682,128.651 ccw(c122.989,128.958) 122.989,128.524 128.905,128.524 ccw(c128.905,131.59) 131.073,129.422 131.445,129.794 ; R12.1@122.682,129.159 127.762,129.159 ccw(c127.762,132.225) 129.93,130.057 C6.1@131.572,131.699 ; R12.1@122.936,129.159 129.859,129.159 ccw(c129.859,131.761) 131.699,129.921 cw(c132.006,130.228) 131.572,130.228 131.572,132.842 ccw(c132.342,132.842) C6.1@132.337,132.072 ; Q4.1@123.571,154.94 127.787,154.94 cw(c127.787,153.822) 128.905,153.822 128.905,153.645 ccw(c130.023,153.645) pad.0@129.505,152.654 ; 125.611,128.524 cw(c125.611,131.707) R12.1@123.36,129.456 ; 126.111,128.524 127.127,128.524 ccw(c127.127,131.59) 129.295,129.422 130.039,130.166 ccw(c127.871,132.334) 130.937,132.334 R11.1@130.937,141.986 ; pad.1@128.651,148.463 130.073,148.463 cw(c130.073,147.345) 131.191,147.345 R11.1@131.191,141.605 ; pad.0@128.778,152.654 131.477,152.654 ccw(c131.731,152.654) 131.731,152.4 133.731,152.4 cw(c133.604,152.4) 133.604,152.273 130.81,152.273 ; pad.1@129.032,148.463 cw(c129.032,146.317) 130.55,147.834 cw(c129.614,146.899) 130.937,146.899 R11.1@130.937,142.24 ; pad.0@129.032,152.781 ccw(c129.952,153.701) 129.952,152.4 ; pad.1@129.159,148.463 cw(c129.159,146.01) 130.893,147.745 cw(c130.175,147.026) 131.191,147.026 R11.1@131.191,142.494 ; pad.0@129.256,152.791 ccw(c129.952,153.216) 129.952,152.4 ; 129.963,130.09 cw(c132.334,127.719) C6.1@132.334,131.072 ; 130.278,152.4 cw(c130.278,153.9) pad.0@129.217,152.839 ; 130.302,129.159 ccw(c128.156,131.305) 131.191,131.305 131.191,132.334 ; 130.937,133.738 ccw(c134.5,133.738) C6.1@131.98,131.218 ; 130.937,136.152 ccw(c136.914,136.152) C6.1@132.688,131.926 ; 130.937,139.977 cw(c132.819,139.977) R11.1@131.488,141.308 ; 130.937,140.59 ccw(c129.922,140.59) R11.1@130.64,141.308 ; 130.937,142.874 cw(c129.922,142.874) R11.1@130.64,142.156 ; 130.937,143.487 ccw(c132.819,143.487) R11.1@131.488,142.156 ; R11.1@131.064,141.732 131.064,132.817 ccw(c132.182,132.817) C6.1@132.182,131.699 ; 131.572,130.027 cw(c132.649,130.027) C6.1@132.434,131.082 ; Q3.2@133.223,152.4 129.952,152.4 ; R12.1@123.36,128.608 cw(c124.691,127.277) 124.691,129.159 ccw(c124.691,127.277) R12.1@123.36,128.608 ; R12.1@123.36,128.608 cw(c124.385,127.583) 124.385,129.032 ; R12.1@123.36,128.608 cw(c124.385,127.583) 124.385,129.032 ; R12.1@123.36,128.608 cw(c124.385,127.583) 124.385,129.032 ; R12.1@123.36,129.456 ccw(c124.078,130.174) 124.078,129.159 cw(c124.078,130.174) R12.1@123.36,129.456 ; R12.1@123.36,129.456 ccw(c125.304,131.4) 125.304,128.651 cw(c125.304,131.4) R12.1@123.36,129.456 ; R12.1@123.36,129.456 ccw(c124.385,130.481) 124.385,129.032 ; R12.1@123.36,129.456 ccw(c124.385,130.481) 124.385,129.032 ; R12.1@123.36,129.456 ccw(c124.385,130.481) 124.385,129.032 ; 128.905,153.593 ccw(c129.971,153.593) pad.0@129.217,152.839 ; 128.905,153.593 ccw(c129.971,153.593) pad.0@129.217,152.839 ; 128.905,153.593 ccw(c129.971,153.593) pad.0@129.217,152.839 ; 128.905,153.593 ccw(c129.971,153.593) pad.0@129.217,152.839 ; 128.905,153.593 ccw(c129.971,153.593) pad.0@129.217,152.839 ; 128.905,153.593 ccw(c129.971,153.593) pad.0@129.217,152.839 ; 128.905,153.593 ccw(c129.971,153.593) pad.0@129.217,152.839 ; 128.905,153.593 ccw(c129.971,153.593) pad.0@129.217,152.839 ; 128.905,153.593 ccw(c129.971,153.593) pad.0@129.217,152.839 ; 128.905,153.593 ccw(c129.971,153.593) pad.0@129.217,152.839 ; R11.1@130.64,141.308 cw(c129.615,140.283) 131.064,140.283 ; R11.1@130.64,141.308 cw(c129.615,140.283) 131.064,140.283 ; R11.1@130.64,142.156 ccw(c129.309,143.487) 131.191,143.487 ; R11.1@130.64,142.156 ccw(c129.309,143.487) 131.191,143.487 ; R11.1@130.64,142.156 ccw(c129.309,143.487) 131.191,143.487 ; 131.064,133.431 ccw(c134.193,133.431) C6.1@131.98,131.218 ; 131.064,133.431 ccw(c134.193,133.431) C6.1@131.98,131.218 ; 131.064,133.431 ccw(c134.193,133.431) C6.1@131.98,131.218 ; 131.064,133.431 ccw(c134.193,133.431) C6.1@131.98,131.218 ; 131.064,133.431 ccw(c134.193,133.431) C6.1@131.98,131.218 ; 131.064,135.845 ccw(c136.607,135.845) C6.1@132.688,131.926 ; 131.064,135.845 ccw(c136.607,135.845) C6.1@132.688,131.926 ; 131.064,135.845 ccw(c136.607,135.845) C6.1@132.688,131.926 ; 131.064,135.845 ccw(c136.607,135.845) C6.1@132.688,131.926 ; 131.064,135.845 ccw(c136.607,135.845) C6.1@132.688,131.926 ; 131.064,140.283 cw(c132.513,140.283) R11.1@131.488,141.308 ; 131.064,140.283 cw(c132.513,140.283) R11.1@131.488,141.308 ; 131.191,142.874 ccw(c132.206,142.874) R11.1@131.488,142.156 ; 131.191,142.874 ccw(c132.206,142.874) R11.1@131.488,142.156 ; 131.191,142.874 ccw(c132.206,142.874) R11.1@131.488,142.156 ; 132.207,130.144 cw(c133.647,130.144) C6.1@132.672,131.204 ; 132.207,130.144 cw(c133.647,130.144) C6.1@132.672,131.204 ; 132.207,130.144 cw(c133.647,130.144) C6.1@132.672,131.204
NetC6_2: C6.2 C7.2 | length 19.9
  Bottom Layer w1: C6.2@135.763,131.699 cw(c135.763,131.064) 136.398,131.064 C7.2@136.398,123.317 ; 136.398,124.958 ccw(c138.039,124.958) C7.2@136.879,123.798 ; C6.2@135.663,131.218 cw(c133.89,129.445) 136.398,129.445 ; C6.2@135.663,131.218 cw(c133.89,129.445) 136.398,129.445 ; C6.2@135.663,131.218 cw(c133.89,129.445) 136.398,129.445 ; C6.2@135.663,131.218 cw(c133.89,129.445) 136.398,129.445 ; C6.2@135.663,131.218 cw(c133.89,129.445) 136.398,129.445
NetC8_1: C8.1 Q3.3 Q4.3 Q5.2 R13.2 R14.1 | length 216.3
  Bottom Layer w1: R14.1@112.649,124.079 119.507,124.079 ; R14.1@112.776,123.825 118.237,123.825 ccw(c118.237,126.891) 120.405,124.723 ccw(c119.507,125.621) 120.777,125.621 120.777,134.366 ; R14.1@112.776,123.952 117.729,123.952 ccw(c117.729,127.018) 119.897,124.85 ccw(c117.773,126.974) 120.777,126.974 120.777,129.032 120.777,130.81 ; 116.205,124.079 117.754,124.079 ccw(c117.754,126.777) 119.662,124.869 119.86,125.067 ccw(c117.952,126.975) 120.65,126.975 120.65,128.949 cw(c121.517,128.949) 120.904,129.562 ; 120.777,125.349 120.777,134.874 cw(c122.047,134.874) 121.92,136.138 cw(c122.047,134.874) 122.047,136.144 122.174,136.144 cw(c122.174,136.525) 121.92,136.241 cw(c122.174,136.525) 121.793,136.525 121.793,149.352 cw(c123.063,149.352) 121.92,149.906 cw(c123.063,149.352) 123.022,150.621 cw(c123.063,149.352) 123.063,150.622 124.968,150.622 ; 120.777,132.207 120.777,134.239 cw(c123.843,134.239) 121.675,136.407 122.047,136.779 ; 120.904,132.207 120.904,132.359 cw(c123.602,132.359) 121.694,134.267 R13.2@123.063,135.636 ; 121.158,134.747 cw(c123.304,134.747) 121.787,136.265 122.174,136.652 ; C8.1@121.158,143.129 121.384,142.903 cw(c119.476,140.995) 122.174,140.995 122.174,135.611 cw(c119.476,135.611) 121.384,133.703 ccw(c122.542,132.545) 120.904,132.545 120.904,129.562 ; 121.666,138.714 ccw(c123.982,138.714) 122.344,137.076 ; 121.666,140.822 ccw(c118.724,140.822) C8.1@120.804,142.902 ; 121.666,145.69 cw(c118.724,145.69) C8.1@120.804,143.61 ; 122.047,139.827 122.047,138.151 ccw(c124.745,138.151) 122.837,136.243 R13.2@123.063,136.017 ; 124.968,150.495 136.55,150.495 ccw(c136.55,151.613) 137.668,151.613 cw(c138.455,151.613) 138.455,152.4 Q5.2@142.113,152.4 ; 125.73,150.368 124.714,150.368 ccw(c124.714,147.302) 122.546,149.47 ccw(c124.67,147.346) 121.666,147.346 121.666,137.213 cw(c121.232,137.213) 121.539,136.906 ccw(c123.072,135.373) 120.904,135.373 120.904,129.562 ; Q3.3@133.477,150.622 135.68,150.622 ccw(c135.68,152.356) 136.906,151.13 137.151,151.375 cw(c139.319,149.207) 139.319,152.273 Q5.2@142.621,152.273 ; Q3.3@133.858,150.368 135.763,150.368 ccw(c135.763,153.434) 137.931,151.266 138.43,151.765 cw(c140.27,149.925) 140.27,152.527 Q5.2@141.986,152.527 ; R14.1@113.2,123.528 cw(c114.531,122.197) 114.531,124.079 ccw(c114.531,122.197) R14.1@113.2,123.528 ; R14.1@113.2,123.528 cw(c113.918,122.81) 113.918,123.825 ; R14.1@113.2,123.528 cw(c114.225,122.503) 114.225,123.952 cw(c114.225,125.401) R14.1@113.2,124.376 ; R14.1@113.2,123.528 cw(c113.918,122.81) 113.918,123.825 ; R14.1@113.2,123.528 cw(c113.918,122.81) 113.918,123.825 ; R14.1@113.2,123.528 cw(c113.918,122.81) 113.918,123.825 ; R14.1@113.2,124.376 ccw(c113.918,125.094) 113.918,124.079 cw(c113.918,125.094) R14.1@113.2,124.376 ; R14.1@113.2,124.376 ccw(c114.531,125.707) 114.531,123.825 ; R14.1@113.2,124.376 ccw(c114.531,125.707) 114.531,123.825 ; R14.1@113.2,124.376 ccw(c114.531,125.707) 114.531,123.825 ; R14.1@113.2,124.376 ccw(c114.531,125.707) 114.531,123.825 ; C8.1@120.804,142.902 cw(c118.418,140.516) 121.793,140.516 ccw(c118.418,140.516) C8.1@120.804,142.902 ; C8.1@120.804,143.61 ccw(c118.418,145.996) 121.793,145.996 cw(c118.418,145.996) C8.1@120.804,143.61 ; 121.496,137.076 ccw(c120.778,137.794) 121.793,137.794 cw(c120.778,137.794) 121.496,137.076 ; 121.496,137.076 ccw(c120.471,138.101) 121.92,138.101 ; 121.496,137.076 ccw(c120.471,138.101) 121.92,138.101 ; 121.496,137.076 ccw(c120.471,138.101) 121.92,138.101 ; 121.92,138.101 ccw(c123.369,138.101) 122.344,137.076 ; 121.92,138.101 ccw(c123.369,138.101) 122.344,137.076 ; 121.92,138.101 ccw(c123.369,138.101) 122.344,137.076 ; 122.344,137.076 cw(c123.675,138.407) 121.793,138.407 ccw(c123.675,138.407) 122.344,137.076 ; Q4.3@123.817,151.003 ccw(c124.737,151.923) 124.737,150.622 cw(c124.737,151.923) Q4.3@123.817,151.003 ; Q4.3@123.817,151.003 ccw(c125.043,152.229) 125.043,150.495 ; Q4.3@123.817,151.003 ccw(c125.043,152.229) 125.043,150.495 ; Q4.3@123.817,151.003 ccw(c125.043,152.229) 125.043,150.495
